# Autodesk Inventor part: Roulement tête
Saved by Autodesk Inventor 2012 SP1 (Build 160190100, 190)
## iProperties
Created: 2014-12
Part Number: Roulement tête
Material: Default
Document SubType Name: Modeling
Designer: Bruno
Density: 1 g/cm^3
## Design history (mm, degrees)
node "Roulement tête1"
node "Roulement tête"
node "Base1"
